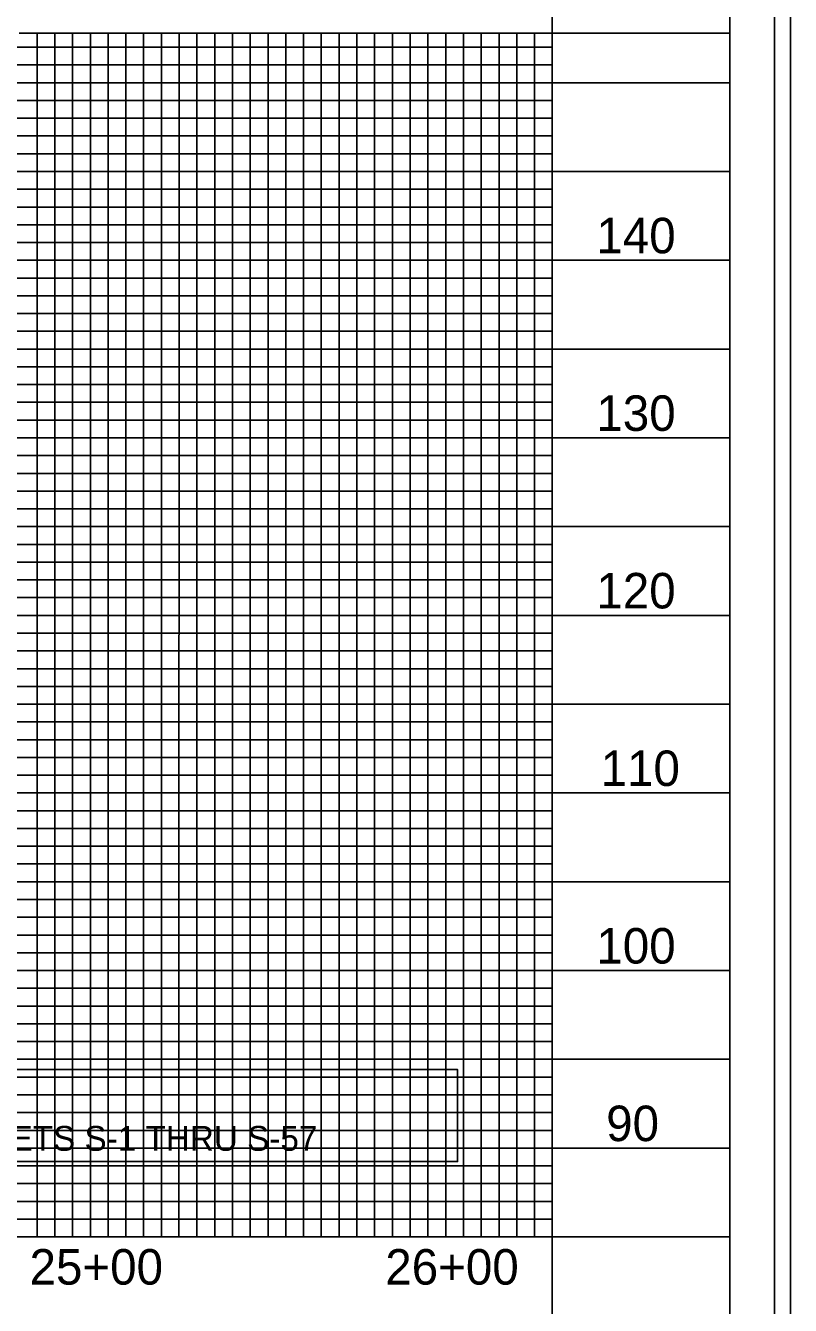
# Model space of a CAD drawing. Extents: x 10070 to 15319, y 8517 to 10343.
# Drawn here: x 14676.7 to 14891.9, y 9072.4 to 9432.8 of the extents above; entities that cross this region are included whole.
import ezdxf

# ---------------------------------------------------------------- set-up
doc = ezdxf.new("R2010")
doc.units = 0
for name, color, linetype in [('Exist Vertical Profile Horizontal Axis Label Major', 7, 'Continuous'), ('Exist Vertical Profile Vertical Axis Label', 7, 'Continuous'), ('Prop Grid Mask', 7, 'Continuous'), ('Prop VPI Label', 7, 'Continuous'), ('Scratch_Level_3', 7, 'Continuous'), ('Scratch_Level_4', 7, 'Continuous'), ('Sheet DOT Grid CELL', 7, 'Continuous'), ('Sheet Layout Profile Border Port 1', 7, 'Continuous'), ('Sheet Plot Border Inside CELL', 7, 'Continuous'), ('Sheet Plot Border Outside CELL', 7, 'Continuous'), ('Sheet Profile CELL', 7, 'Continuous'), ('Sheet Profile Grid Major CELL', 7, 'Continuous'), ('Sheet Profile Grid Middle CELL', 7, 'Continuous'), ('Sheet Profile Grid Minor CELL', 7, 'Continuous'), ('Sheet Sticker Exception Certification CELL', 7, 'Continuous')]:
    doc.layers.add(name, color=color, linetype=linetype)

msp = doc.modelspace()

# ---------------------------------------------------------------- linework, layer by layer
at = {"layer": 'Prop Grid Mask'}
msp.add_lwpolyline([(14506.36, 9112.92), (14506.36, 9138.82), (14798.3, 9138.82), (14798.3, 9112.92)], close=True, dxfattribs=at)
at = {"layer": 'Scratch_Level_3'}
msp.add_lwpolyline([(13374.94, 9591.73), (14824.91, 9591.73), (14824.91, 8566.73), (13374.94, 8566.73)], close=True, dxfattribs=at)
at = {"layer": 'Scratch_Level_4'}
msp.add_lwpolyline([(13374.94, 9591.73), (14874.94, 9591.73), (14874.94, 9091.73), (13374.94, 9091.73)], close=True, dxfattribs=at)
at = {"layer": 'Sheet DOT Grid CELL'}
for p, q in [((14724.94, 9091.73), (14724.94, 9430.68)), ((14774.94, 9091.73), (14774.94, 9430.68)), ((14824.94, 9091.73), (14824.94, 9430.68)), ((14874.94, 9391.73), (13374.94, 9391.73)), ((14874.94, 9341.73), (13374.94, 9341.73)), ((14874.94, 9291.73), (13374.94, 9291.73)), ((14874.94, 9241.73), (13374.94, 9241.73)), ((14874.94, 9191.73), (13374.94, 9191.73)), ((14874.94, 9141.73), (13374.94, 9141.73))]:
    msp.add_line(p, q, dxfattribs=at)
at = {"layer": 'Sheet Layout Profile Border Port 1'}
msp.add_lwpolyline([(13424.94, 9430.68), (13424.94, 9091.73), (14824.94, 9091.73), (14824.94, 9430.68)], dxfattribs=at)
at = {"layer": 'Sheet Plot Border Inside CELL'}
msp.add_lwpolyline([(13220.94, 8539.18), (14887.44, 8539.18), (14887.44, 9594.28), (13220.94, 9594.28)], close=True, dxfattribs=at)
at = {"layer": 'Sheet Plot Border Outside CELL'}
msp.add_lwpolyline([(13207.94, 8516.73), (14891.94, 8516.73), (14891.94, 9616.73), (13207.94, 9616.73)], close=True, dxfattribs=at)
at = {"layer": 'Sheet Profile CELL'}
msp.add_line((13374.94, 9091.73), (14874.94, 9091.73), dxfattribs=at)
msp.add_lwpolyline([(14874.94, 9591.73), (13374.94, 9591.73), (13374.94, 8541.73), (14874.94, 8541.73)], close=True, dxfattribs=at)
at = {"layer": 'Sheet Profile Grid Major CELL'}
for points in [[(14824.94, 9430.68), (14824.94, 9091.73), (14874.94, 9091.73), (14874.94, 9441.73)], [(14724.94, 9430.68), (14724.94, 9091.73), (14774.94, 9091.73), (14774.94, 9091.73), (14774.94, 9430.68)], [(14874.94, 9391.73), (13374.94, 9391.73), (13374.94, 9341.73), (14874.94, 9341.73)], [(14874.94, 9291.73), (13374.94, 9291.73), (13374.94, 9241.73), (14874.94, 9241.73)], [(14874.94, 9191.73), (13374.94, 9191.73), (13374.94, 9191.73), (13374.94, 9141.73), (14874.94, 9141.73)]]:
    msp.add_lwpolyline(points, dxfattribs=at)
at = {"layer": 'Sheet Profile Grid Middle CELL'}
for points in [[(14249.94, 9091.73), (14299.94, 9091.73), (14299.94, 9591.73), (14349.94, 9591.73), (14349.94, 9091.73), (14399.94, 9091.73), (14399.94, 9591.73), (14449.94, 9591.73), (14449.94, 9091.73), (14499.94, 9091.73), (14499.94, 9591.73), (14549.94, 9591.73), (14549.94, 9091.73), (14599.94, 9091.73), (14599.94, 9591.73), (14649.94, 9591.73), (14649.94, 9091.73), (14699.94, 9091.73), (14699.94, 9430.68)], [(14699.94, 9354.53), (14699.94, 9091.73), (14749.94, 9091.73), (14749.94, 9430.68)], [(14749.94, 9354.53), (14749.94, 9091.73), (14799.94, 9091.73), (14799.94, 9430.68)], [(14874.94, 9416.73), (13374.94, 9416.73), (13374.94, 9366.73), (14699.94, 9366.73)], [(14699.94, 9366.73), (14874.94, 9366.73)], [(14874.94, 9316.73), (13374.94, 9316.73), (13374.94, 9266.73), (14874.94, 9266.73)], [(14874.94, 9216.73), (13374.94, 9216.73), (13374.94, 9166.73), (14874.94, 9166.73)], [(14874.94, 9116.73), (13374.94, 9116.73)]]:
    msp.add_lwpolyline(points, dxfattribs=at)
at = {"layer": 'Sheet Profile Grid Minor CELL'}
for p, q in [((13424.94, 9426.73), (14824.94, 9426.73)), ((14824.94, 9406.73), (13424.94, 9406.73)), ((13424.94, 9401.73), (14824.94, 9401.73)), ((14824.94, 9381.73), (13424.94, 9381.73)), ((13424.94, 9376.73), (14824.94, 9376.73)), ((14824.94, 9356.73), (13424.94, 9356.73)), ((13424.94, 9351.73), (14824.94, 9351.73)), ((14824.94, 9346.73), (13424.94, 9346.73)), ((13424.94, 9336.73), (14824.94, 9336.73)), ((14824.94, 9331.73), (13424.94, 9331.73)), ((13424.94, 9326.73), (14824.94, 9326.73)), ((14824.94, 9321.73), (13424.94, 9321.73)), ((13424.94, 9311.73), (14824.94, 9311.73)), ((14824.94, 9306.73), (13424.94, 9306.73)), ((13424.94, 9301.73), (14824.94, 9301.73)), ((14824.94, 9296.73), (13424.94, 9296.73)), ((13424.94, 9286.73), (14824.94, 9286.73)), ((14824.94, 9281.73), (13424.94, 9281.73)), ((13424.94, 9276.73), (14824.94, 9276.73)), ((14824.94, 9271.73), (13424.94, 9271.73)), ((13424.94, 9261.73), (14824.94, 9261.73)), ((14824.94, 9256.73), (13424.94, 9256.73)), ((13424.94, 9251.73), (14824.94, 9251.73)), ((14824.94, 9246.73), (13424.94, 9246.73)), ((13424.94, 9236.73), (14824.94, 9236.73)), ((14824.94, 9231.73), (13424.94, 9231.73)), ((13424.94, 9226.73), (14824.94, 9226.73)), ((14824.94, 9221.73), (13424.94, 9221.73)), ((13424.94, 9211.73), (14824.94, 9211.73)), ((14824.94, 9206.73), (13424.94, 9206.73)), ((14824.94, 9201.73), (13424.94, 9201.73)), ((14824.94, 9196.73), (13424.94, 9196.73)), ((13424.94, 9186.73), (14824.94, 9186.73)), ((14824.94, 9181.73), (13424.94, 9181.73)), ((13424.94, 9176.73), (14824.94, 9176.73)), ((14824.94, 9171.73), (13424.94, 9171.73)), ((13424.94, 9161.73), (14824.94, 9161.73)), ((14824.94, 9156.73), (13424.94, 9156.73)), ((13424.94, 9151.73), (14824.94, 9151.73)), ((14824.94, 9146.73), (13424.94, 9146.73)), ((13424.94, 9136.73), (14824.94, 9136.73)), ((14824.94, 9131.73), (13424.94, 9131.73)), ((13424.94, 9126.73), (14824.94, 9126.73)), ((14824.94, 9121.73), (13424.94, 9121.73)), ((13424.94, 9111.73), (14824.94, 9111.73)), ((14824.94, 9106.73), (13424.94, 9106.73)), ((13424.94, 9101.73), (14824.94, 9101.73))]:
    msp.add_line(p, q, dxfattribs=at)
for points in [[(14679.94, 9430.68), (14679.94, 9091.73), (14684.94, 9091.73), (14684.94, 9430.68)], [(14689.94, 9430.68), (14689.94, 9091.73), (14694.94, 9091.73), (14694.94, 9430.68)], [(14704.94, 9430.68), (14704.94, 9091.73), (14704.94, 9091.73), (14709.94, 9091.73), (14714.94, 9091.73), (14714.94, 9430.68)], [(14709.94, 9430.68), (14709.94, 9091.73)], [(14719.93, 9430.68), (14719.84, 9091.78), (14724.84, 9091.78), (14729.94, 9091.73), (14729.94, 9430.68)], [(14729.94, 9354.53), (14729.94, 9091.73), (14734.94, 9091.73), (14734.94, 9430.68)], [(14739.94, 9430.68), (14739.94, 9091.73), (14744.94, 9091.73), (14744.94, 9430.68)], [(14754.94, 9430.68), (14754.94, 9091.73), (14759.94, 9091.73), (14759.94, 9430.68)], [(14764.94, 9430.68), (14764.94, 9091.73), (14769.94, 9091.73), (14769.94, 9430.68)], [(14779.94, 9430.68), (14779.94, 9091.73), (14784.94, 9091.73), (14784.94, 9430.68)], [(14789.94, 9430.68), (14789.94, 9091.73), (14794.94, 9091.73), (14794.94, 9430.68)], [(14804.94, 9430.68), (14804.94, 9091.73), (14809.94, 9091.73), (14809.94, 9430.68)], [(14814.94, 9430.68), (14814.94, 9091.73), (14819.94, 9091.73), (14819.94, 9430.68)], [(14824.94, 9421.73), (13424.94, 9421.73), (13424.94, 9411.73), (14824.94, 9411.73)], [(14824.94, 9396.73), (13424.94, 9396.73), (13424.94, 9386.73), (14824.94, 9386.73)], [(14824.94, 9371.73), (13424.94, 9371.73), (13424.94, 9361.73), (14824.94, 9361.73)], [(14824.94, 9096.73), (13424.94, 9096.73)]]:
    msp.add_lwpolyline(points, dxfattribs=at)
at = {"layer": 'Sheet Sticker Exception Certification CELL'}
for p, q in [((14874.93, 9454.16), (14874.93, 9430.66)), ((14874.93, 9454.16), (14874.93, 9430.66)), ((14874.93, 9430.68), (14674.89, 9430.68)), ((14874.93, 9430.68), (14674.89, 9430.68))]:
    msp.add_line(p, q, dxfattribs=at)

# ---------------------------------------------------------------- texts
at = {"layer": 'Exist Vertical Profile Horizontal Axis Label Major'}
for s, p in [('25+00', (14677.83, 9078.29)), ('26+00', (14777.94, 9078.29))]:
    msp.add_text(s, height=10, dxfattribs=at).set_placement(p)
at = {"layer": 'Exist Vertical Profile Vertical Axis Label'}
for s, p in [('140', (14837.34, 9368.69)), ('130', (14837.34, 9318.69)), ('120', (14837.34, 9268.69)), ('110', (14838.54, 9218.69)), ('100', (14837.34, 9168.69)), ('90', (14840.1, 9118.69))]:
    msp.add_text(s, height=10, dxfattribs=at).set_placement(p)
at = {"layer": 'Prop VPI Label'}
msp.add_text('FOR STRUCTURE PLANS SEE SHEETS S-1 THRU S-57', height=7, dxfattribs=at).set_placement((14515.93, 9115.97))

doc.saveas('drawing.dxf')
